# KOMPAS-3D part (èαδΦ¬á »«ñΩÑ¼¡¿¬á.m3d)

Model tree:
1. Эскиз:1
2. Операция выдавливания:1
     Расстояние 1 = 6.75
3. Эскиз:2
4. Вырезать элемент выдавливания:1
     Расстояние 2 = 9.5; Расстояние 1 = 5
5. Фаска:1
     Угол = 45; Длина 1 = 1; Длина 2 = 1
